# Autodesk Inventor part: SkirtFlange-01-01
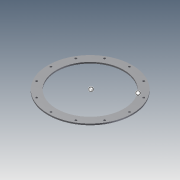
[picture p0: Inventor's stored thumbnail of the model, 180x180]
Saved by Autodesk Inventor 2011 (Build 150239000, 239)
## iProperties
Created: 2010-06
Part Number: SkirtFlange-01-01
Document SubType Name: Modeling
Designer: mklassen
Density: 1 g/cm^3
OD: 36.000 in
THK: 0.500 in
WDT: 3.000 in
BHN: 12.000 ul
BHD: 0.750 in
BCD: 20.000 in
Author: mklassen
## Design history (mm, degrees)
sketch "skSkirtFlange"
  geometry: C1 r 457.2 at (0, 0); C2 r 533.4 at (0, 0); 1 further point
  constraints: 2 centre point, 2 coincident
  dimensions: "d0" = 76.2 radial gap between concentric circles of C2 C1 (derived); "d1" = 914.4 diameter of C1 (derived)
extrude "SkirtFlange" new body sketch "skSkirtFlange" stored distance "d2" = 12.7 (derived); taper "d3" = 0 deg
sketch "skBoltHole"
  geometry: C1 r 457.2 at (0, 0) reference; 2 further points
  constraints: 1 coincident, 1 vertical alignment
  dimensions: "d7" = 508 distance of point (0, 508) point (0, 0) (= BCD)
hole "BoltHole" sketch "skBoltHole" at (0, 508) diameter "d8" = 19.05 (derived); stored, may be unused: countersink angle "d12" = 82 deg, drill point angle "d14" = 118 deg; dims "d9" = 19.05, "d10" = 9.525, "d11" = 6.35, "d13" = 25.4
pattern_circular "BoltCircle" dims angle "d16" = 360 deg
body "Solid1"
other parameters: "BCD" = 508 [user parameter; used in 2 equation terms], "d4" = 0, "d5" = 0, "d6" = 0
